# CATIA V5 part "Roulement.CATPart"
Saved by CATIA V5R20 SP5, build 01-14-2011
Part number: Skl_Roulement
Publications: "Plan xy", "Axe_pivot_roulement/gouv"
Bounding box of the stored display mesh (mm): x 0 to 0, y 187.727 to 298.864, z -10 to 150
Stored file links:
  U:\2A\CFAO\dossier sans titre\Roulement.CATPart
  U:\2A\CFAO\dossier sans titre\Skl_gouvernail.CATProduct
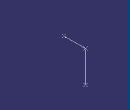
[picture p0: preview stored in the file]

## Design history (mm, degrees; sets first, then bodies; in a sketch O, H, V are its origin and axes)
Set1
  Point1 "Point.24": linked copy from another document
  Point2 "Point.23": linked copy from another document
  Point3: linked copy from another document
Body1 (main body)
  Line1 "Axe_pivot_roulement/gouv": type PtPt, FirstPoint Point1, SecondPoint Point2
  Line2: type PtPt, FirstPoint Point1, SecondPoint Point3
